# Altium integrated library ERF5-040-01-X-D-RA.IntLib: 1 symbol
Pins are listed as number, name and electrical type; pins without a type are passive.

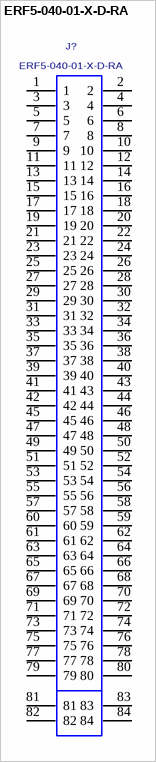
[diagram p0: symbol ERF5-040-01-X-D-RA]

## ERF5-040-01-X-D-RA
designator J?
0.5mm Right Angle Socket Assembly, 80 Pins.; MANUFACTURER: SAMTEC
footprint ERF5-040-01-X-D-RA
pins: 1, 2, 3, 4, 5, 6, 7, 8, 9, 10, 11, 12, 13, 14, 15, 16, 17, 18, 19, 20, 21, 22, 23, 24, 25, 26, 27, 28, 29, 30, 31, 32, 33, 34, 35, 36, 37, 38, 39, 40, 41, 42, 43, 44, 45, 46, 47, 48, 49, 50, 51, 52, 53, 54, 55, 56, 57, 58, 59, 60, 61, 62, 63, 64, 65, 66, 67, 68, 69, 70, 71, 72, 73, 74, 75, 76, 77, 78, 79, 80, 81, 82, 83, 84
